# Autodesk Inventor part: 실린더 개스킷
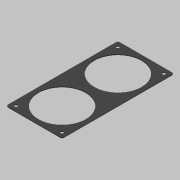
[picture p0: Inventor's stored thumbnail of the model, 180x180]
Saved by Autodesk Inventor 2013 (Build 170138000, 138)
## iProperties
Created: 2019-08
Part Number: 실린더 개스킷
Material: 고무
Document SubType Name: Modeling
Designer: mduedu
Density: 1 g/cm^3
Author: mduedu
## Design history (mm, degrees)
sketch "스케치1"
  geometry: L1 (42.5, -42.5)-(-42.5, -42.5); L2 (-42.5, -42.5)-(-42.5, 127.5); L3 (-42.5, 127.5)-(42.5, 127.5); L4 (42.5, 127.5)-(42.5, -42.5); 2 further points
  constraints: 8 end point, 2 parallel, 1 horizontal, 1 midpoint, 1 perpendicular, 1 vertical alignment
  dimensions: "d1" = 85 distance of L1.start L1.end; "d3" = 170 distance of L3.end L1.start; "d4" = 42.5 distance from line of L1 point (0, 0)
extrude "돌출1" new body sketch "스케치1" distance "d5" = 1; taper "d6" = 0 deg
sketch "스케치2"
  geometry: C1 r 36 at (0, 0); C2 r 36 at (0, 85); 1 further point
  constraints: 2 centre point, 1 coincident, 1 vertical alignment
  dimensions: "d7" = 72 diameter of C1; "d8" = 72 diameter of C2; "d9" = 85 distance of C2.centre point (0, 0)
extrude "돌출2" cut sketch "스케치2" stored distance "d10" = 1; taper "d11" = 0 deg
sketch "스케치3"
  geometry: L1 (-35, -35)-(35, -35); L2 (35, -35)-(35, 35); L3 (35, 35)-(-35, 35); L4 (-35, 35)-(-35, -35); L5 (-35, -35)-(35, 35); L6 (35, -35)-(-35, 35); L7 (-35, 50)-(35, 50); L8 (35, 50)-(35, 120); L9 (35, 120)-(-35, 120); L10 (-35, 120)-(-35, 50); L11 (-35, 50)-(35, 120); L12 (35, 50)-(-35, 120); C1 r 36 at (0, 85) reference; 5 further points
  constraints: 24 end point, 4 coincident, 4 midpoint, 4 parallel, 2 horizontal, 2 perpendicular
  dimensions: "d12" = 70 distance of L3.end L2.end; "d13" = 70 distance of L2.end L1.end; "d14" = 70 distance of L9.end L8.end; "d15" = 70 distance of L8.end L7.end
hole "구멍1" sketch "스케치3" at (35, -35), (-35, -35), (-35, 120), (35, 120) diameter "d16" = 5; stored, may be unused: countersink angle "d20" = 90 deg, drill point angle "d22" = 118 deg; dims "d17" = 6, "d18" = 4, "d19" = 2, "d21" = 8
fillet "모깎기1" dims "d23" = 3
node "솔리드2"
node "솔리드1"
